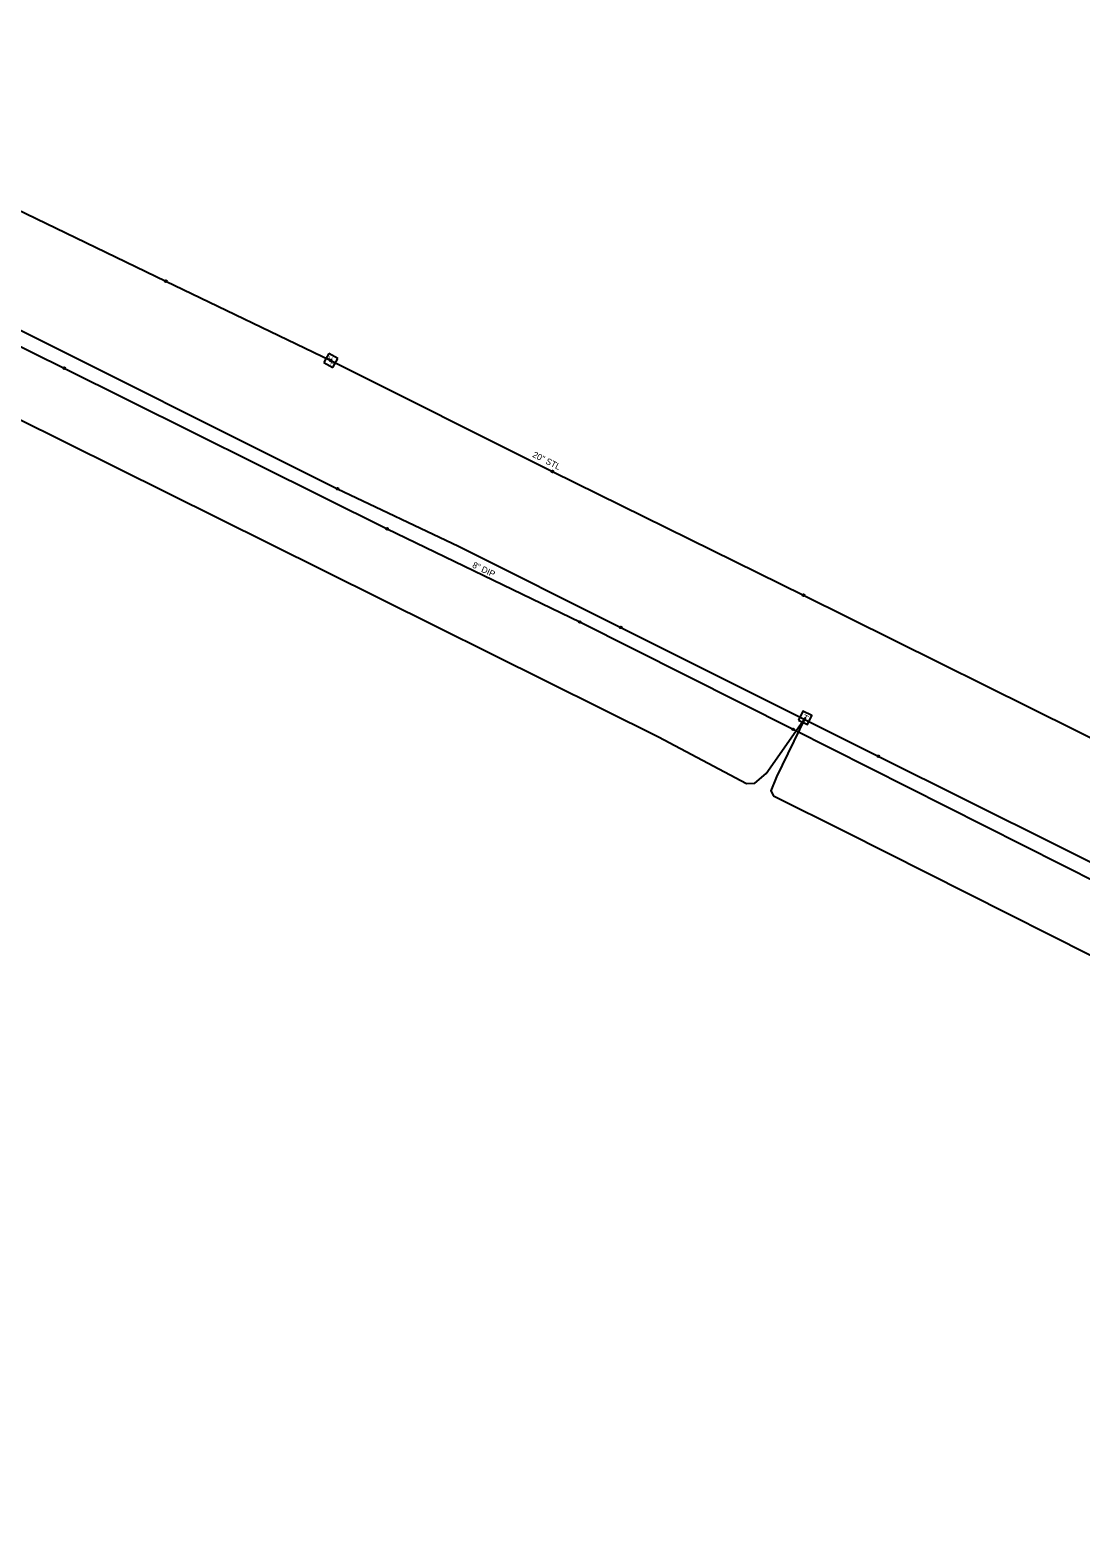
# Model space of a CAD drawing. Extents: x 2244485 to 2250986, y 199568 to 203007.
# Drawn here: x 2246567 to 2247155, y 201272 to 202115 of the extents above; entities that cross this region are included whole.
import ezdxf

# ---------------------------------------------------------------- set-up
doc = ezdxf.new("R2010")
doc.units = 0
for name, color, linetype in [('Default', 7, 'Continuous'), ('Exist Utilities Gas Meter CELL', 7, 'Continuous'), ('Exist Utilities Gas UG Line SUE LOS B', 7, 'Continuous'), ('Exist Utilities Gas UG Line SUE LOS B Text', 7, 'Continuous'), ('Exist Utilities Sanitary Sewer Forced Main SUE LOS B', 7, 'Continuous'), ('Exist Utilities Sanitary Sewer Forced Main SUE LOS B Text', 7, 'Continuous'), ('Exist Utilities Telephone Pedestal CELL', 7, 'Continuous'), ('Exist Utilities Telephone UG Cable SUE LOS C', 7, 'Continuous'), ('Exist Utilities Telephone UG FO SUE LOS B', 7, 'Continuous')]:
    doc.layers.add(name, color=color, linetype=linetype)

# ---------------------------------------------------------------- blocks, each defined once
blk = doc.blocks.new('SurveyPointCell')
at = {"layer": 'Default'}
for p, q in [((-0.5, 0), (0.5, 0)), ((0, -0.5), (0, 0.5))]:
    blk.add_line(p, q, dxfattribs=at)
blk.add_circle((0, 0), 0.5, dxfattribs=at)

msp = doc.modelspace()

# ---------------------------------------------------------------- linework, layer by layer
at = {"layer": 'Exist Utilities Gas Meter CELL'}
for p, q in [((2246733.84, 201934.22), (2246731.07, 201929.21)), ((2246731.07, 201929.21), (2246736.08, 201926.44)), ((2246738.85, 201931.45), (2246733.84, 201934.22)), ((2246734.96, 201930.33), (2246734.96, 201930.33)), ((2246736.08, 201926.44), (2246738.85, 201931.45))]:
    msp.add_line(p, q, dxfattribs=at)
at = {"layer": 'Exist Utilities Gas UG Line SUE LOS B'}
msp.add_lwpolyline([(2244658.96, 202958.49), (2244721.96, 202928.3), (2244863.47, 202856.19), (2244912.51, 202831.57), (2245070.07, 202752.33), (2245256.14, 202659.91), (2245331.4, 202622.29), (2245514.38, 202531.76), (2245606.53, 202488.05), (2245652.12, 202465.42), (2245827.69, 202375.08), (2246001.01, 202291.84), (2246162.3, 202211.17), (2246329.12, 202125.74), (2246513.99, 202036.93), (2246642.7, 201974.75), (2246734.96, 201930.33), (2246858.92, 201868.26), (2246999.42, 201799.12), (2247177.53, 201710.71), (2247331.7, 201633.3), (2247466.92, 201567.22), (2247602.4, 201501.88), (2247749.1, 201426.01)], dxfattribs=at)
at = {"layer": 'Exist Utilities Sanitary Sewer Forced Main SUE LOS B'}
msp.add_lwpolyline([(2245613.42, 202432.81), (2245612.33, 202430.62), (2245623.88, 202401.25), (2245742.14, 202343.1), (2245917.37, 202257.79), (2246026.41, 202202.34), (2246210.46, 202111.93), (2246345.24, 202046.28), (2246501.59, 201967.74), (2246585.87, 201926.12), (2246766.44, 201836.2), (2246874.3, 201784.12), (2246993.56, 201724.08), (2247186.6, 201626.85), (2247291.7, 201574.36), (2247419.93, 201509.91), (2247528.38, 201455.85), (2247631.36, 201405.97), (2247735.41, 201350.67), (2247801.59, 201317.51)], dxfattribs=at)
at = {"layer": 'Exist Utilities Telephone Pedestal CELL'}
msp.add_line((2247000.3, 201730.52), (2247000.3, 201730.52), dxfattribs=at)
msp.add_lwpolyline([(2246996.64, 201729.11), (2247001.71, 201726.75), (2247004.08, 201731.81), (2246999.01, 201734.18), (2246996.64, 201729.11)], dxfattribs=at)
at = {"layer": 'Exist Utilities Telephone UG Cable SUE LOS C'}
msp.add_lwpolyline([(2246473.42, 201940.75), (2246700.68, 201828.04), (2246918.29, 201719.79), (2246967.49, 201693.76), (2246972.21, 201694.04), (2246978.56, 201699.41), (2247000.3, 201730.52), (2246984.26, 201697.47), (2246981.09, 201689.73), (2246982.67, 201686.82), (2247023.03, 201666.72), (2247227.98, 201563.38), (2247472.41, 201444.11), (2247675.02, 201342.94), (2247679.49, 201343.77), (2247683.14, 201348.6), (2247701.3, 201380.55), (2247688.18, 201348.67), (2247685.95, 201341.92), (2247686.97, 201337.82), (2247821.99, 201271.82)], dxfattribs=at)
at = {"layer": 'Exist Utilities Telephone UG FO SUE LOS B'}
msp.add_lwpolyline([(2246544.1, 201955.85), (2246738.78, 201858.63), (2246806.46, 201826.48), (2246897.21, 201781.07), (2247041.24, 201709.01), (2247192.04, 201633.96), (2247260.63, 201598.54), (2247302.66, 201579.85), (2247395.02, 201532.05), (2247442.43, 201506.85), (2247503.92, 201478.03), (2247618.67, 201423.77), (2247677.96, 201393.41), (2247734.6, 201364.13), (2247798.15, 201331.66)], dxfattribs=at)

# ---------------------------------------------------------------- block references
at = {"layer": 'Default'}
for p in [(2246642.7, 201974.75), (2246734.96, 201930.33), (2246585.87, 201926.12), (2246858.92, 201868.26), (2246738.78, 201858.63), (2246766.44, 201836.2), (2246999.42, 201799.12), (2246874.3, 201784.12), (2246897.21, 201781.07), (2246993.56, 201724.08), (2247041.24, 201709.01)]:
    msp.add_blockref('SurveyPointCell', p, dxfattribs=at)

# ---------------------------------------------------------------- texts
at = {"layer": 'Exist Utilities Gas Meter CELL'}
for p in [(2246732.85, 201930.82), (2246734.39, 201928.29)]:
    msp.add_text('H', height=2.5, rotation=331.07712, dxfattribs=at).set_placement(p)
at = {"layer": 'Exist Utilities Gas UG Line SUE LOS B Text'}
msp.add_text('20" STL', height=3.5, rotation=333.09153, dxfattribs=at).set_placement((2246847.49, 201876.58))
at = {"layer": 'Exist Utilities Sanitary Sewer Forced Main SUE LOS B Text'}
msp.add_text('8" DIP', height=3.5, rotation=334.4319, dxfattribs=at).set_placement((2246813.77, 201814.79))
at = {"layer": 'Exist Utilities Telephone Pedestal CELL'}
msp.add_text('T', height=3.42, rotation=334.9707, dxfattribs=at).set_placement((2246998.55, 201729.45))

doc.saveas('drawing.dxf')
